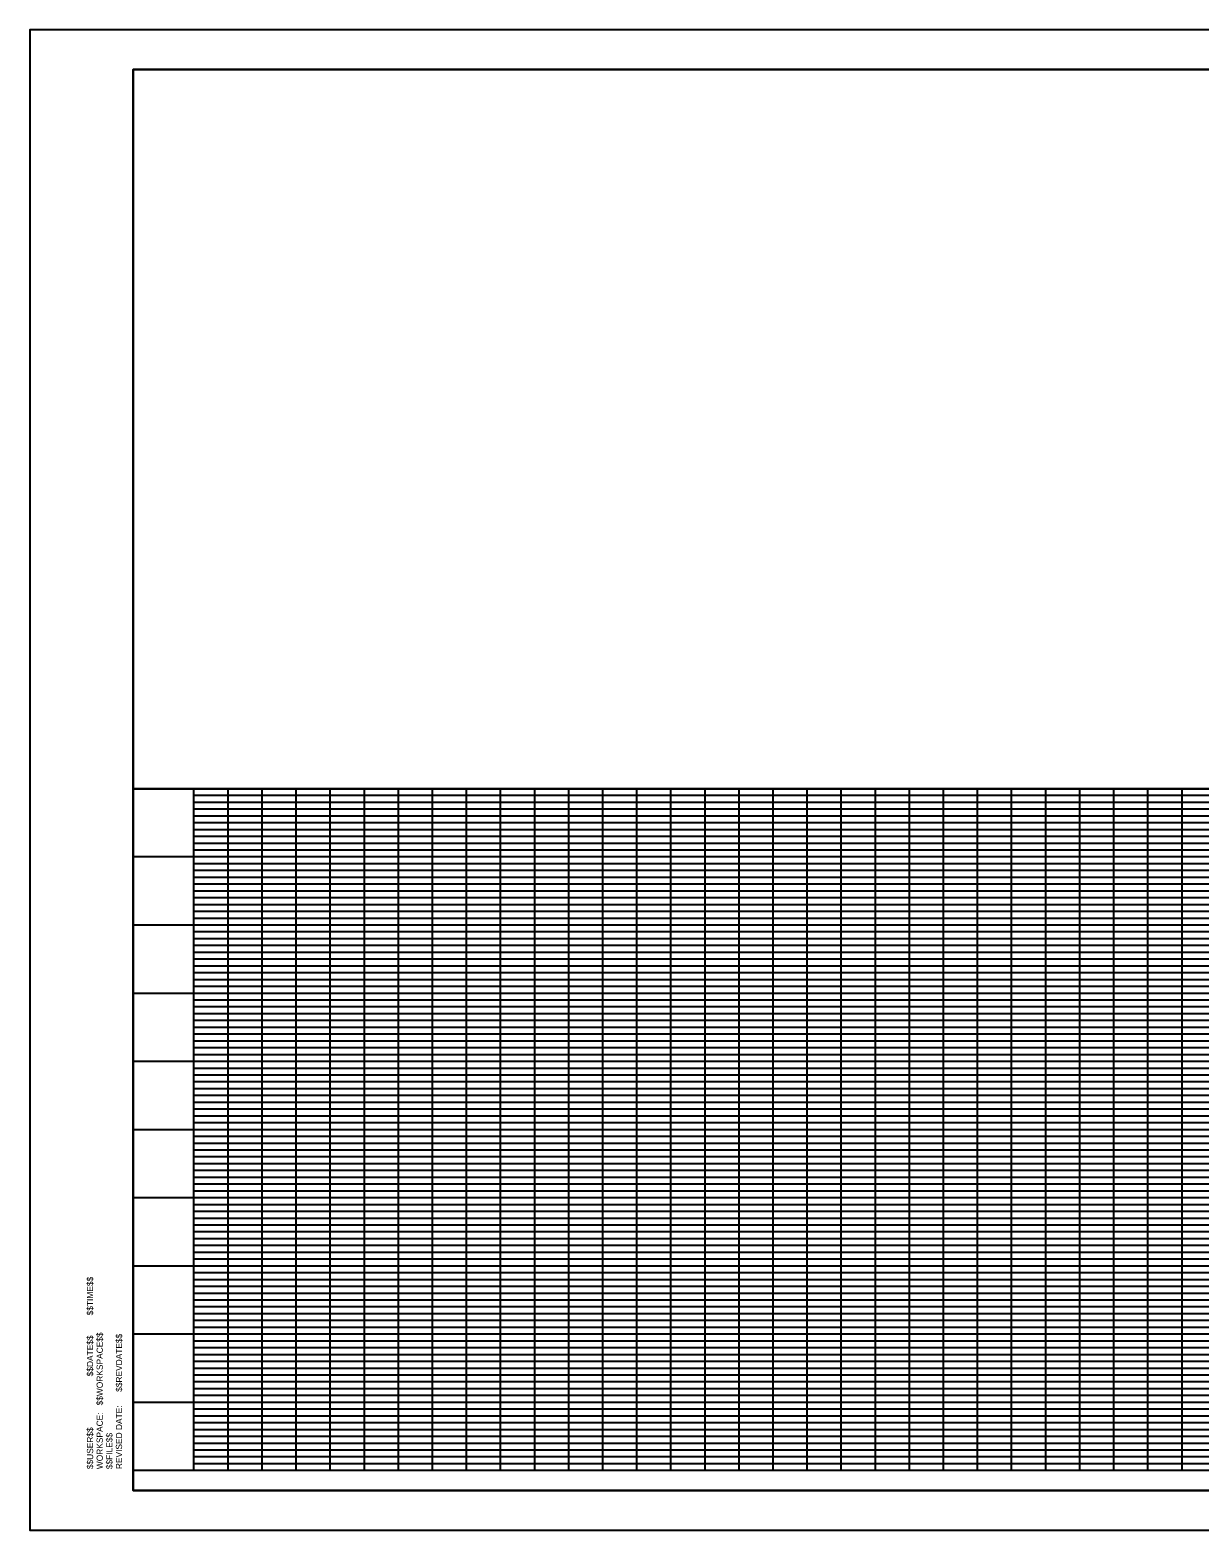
# Model space of a CAD drawing. Extents: x 0 to 1228740, y 0 to 152440.
# Drawn here: x 0 to 17.16, y 0 to 22 of the extents above; entities that cross this region are included whole.
import ezdxf

# ---------------------------------------------------------------- set-up
doc = ezdxf.new("R2010")
doc.units = 0
for name, color, linetype in [('G-TBLK', 7, 'Continuous'), ('R_Border', 7, 'Continuous'), ('R_Grid', 7, 'Continuous'), ('R_No Plot', 7, 'Continuous')]:
    doc.layers.add(name, color=color, linetype=linetype)

msp = doc.modelspace()

# ---------------------------------------------------------------- linework, layer by layer
at = {"layer": 'R_Border'}
for p, q in [((1.516, 21.423), (33.423, 21.423)), ((1.516, 0.577), (1.516, 21.423)), ((33.423, 0.577), (1.516, 0.577))]:
    msp.add_line(p, q, dxfattribs=at)
msp.add_lwpolyline([(34, 22), (0, 22), (0, 0), (34, 0)], close=True, dxfattribs=at)
at = {"layer": 'R_Grid'}
for p, q in [((33.423, 10.871), (1.516, 10.871)), ((2.407, 0.871), (2.407, 10.871)), ((2.907, 0.871), (2.907, 10.871)), ((3.407, 0.871), (3.407, 10.871)), ((3.907, 0.871), (3.907, 10.871)), ((4.407, 0.871), (4.407, 10.871)), ((4.907, 0.871), (4.907, 10.871)), ((5.407, 0.871), (5.407, 10.871)), ((5.907, 0.871), (5.907, 10.871)), ((6.407, 0.871), (6.407, 10.871)), ((6.907, 0.871), (6.907, 10.871)), ((7.407, 0.871), (7.407, 10.871)), ((7.907, 0.871), (7.907, 10.871)), ((8.407, 0.871), (8.407, 10.871)), ((8.907, 0.871), (8.907, 10.871)), ((9.407, 0.871), (9.407, 10.871)), ((9.907, 0.871), (9.907, 10.871)), ((10.407, 0.871), (10.407, 10.871)), ((10.907, 0.871), (10.907, 10.871)), ((11.407, 0.871), (11.407, 10.871)), ((11.907, 0.871), (11.907, 10.871)), ((12.407, 0.871), (12.407, 10.871)), ((12.907, 0.871), (12.907, 10.871)), ((13.407, 0.871), (13.407, 10.871)), ((13.907, 0.871), (13.907, 10.871)), ((14.407, 0.871), (14.407, 10.871)), ((14.907, 0.871), (14.907, 10.871)), ((15.407, 0.871), (15.407, 10.871)), ((15.907, 0.871), (15.907, 10.871)), ((16.407, 0.871), (16.407, 10.871)), ((16.907, 0.871), (16.907, 10.871)), ((32.407, 10.771), (2.407, 10.771)), ((32.407, 10.671), (2.407, 10.671)), ((32.407, 10.571), (2.407, 10.571)), ((32.407, 10.471), (2.407, 10.471)), ((32.407, 10.371), (2.407, 10.371)), ((32.407, 10.271), (2.407, 10.271)), ((32.407, 10.171), (2.407, 10.171)), ((32.407, 10.071), (2.407, 10.071)), ((32.407, 9.971), (2.407, 9.971)), ((33.423, 9.871), (1.516, 9.871)), ((32.407, 9.771), (2.407, 9.771)), ((32.407, 9.671), (2.407, 9.671)), ((32.407, 9.571), (2.407, 9.571)), ((32.407, 9.471), (2.407, 9.471)), ((32.407, 9.371), (2.407, 9.371)), ((32.407, 9.271), (2.407, 9.271)), ((32.407, 9.171), (2.407, 9.171)), ((32.407, 9.071), (2.407, 9.071)), ((33.423, 8.871), (1.516, 8.871)), ((32.407, 8.971), (2.407, 8.971)), ((32.407, 8.771), (2.407, 8.771)), ((32.407, 8.671), (2.407, 8.671)), ((32.407, 8.571), (2.407, 8.571)), ((32.407, 8.471), (2.407, 8.471)), ((32.407, 8.371), (2.407, 8.371)), ((32.407, 8.271), (2.407, 8.271)), ((32.407, 8.171), (2.407, 8.171)), ((32.407, 8.071), (2.407, 8.071)), ((32.407, 7.971), (2.407, 7.971)), ((33.423, 7.871), (1.516, 7.871)), ((32.407, 7.771), (2.407, 7.771)), ((32.407, 7.671), (2.407, 7.671)), ((32.407, 7.571), (2.407, 7.571)), ((32.407, 7.471), (2.407, 7.471)), ((32.407, 7.371), (2.407, 7.371)), ((32.407, 7.271), (2.407, 7.271)), ((32.407, 7.171), (2.407, 7.171)), ((32.407, 7.071), (2.407, 7.071)), ((33.423, 6.871), (1.516, 6.871)), ((32.407, 6.971), (2.407, 6.971)), ((32.407, 6.771), (2.407, 6.771)), ((32.407, 6.671), (2.407, 6.671)), ((32.407, 6.571), (2.407, 6.571)), ((32.407, 6.471), (2.407, 6.471)), ((32.407, 6.371), (2.407, 6.371)), ((32.407, 6.271), (2.407, 6.271)), ((32.407, 6.171), (2.407, 6.171)), ((32.407, 6.071), (2.407, 6.071)), ((32.407, 5.971), (2.407, 5.971)), ((33.423, 5.871), (1.516, 5.871)), ((32.407, 5.771), (2.407, 5.771)), ((32.407, 5.671), (2.407, 5.671)), ((32.407, 5.571), (2.407, 5.571)), ((32.407, 5.471), (2.407, 5.471)), ((32.407, 5.371), (2.407, 5.371)), ((32.407, 5.271), (2.407, 5.271)), ((32.407, 5.171), (2.407, 5.171)), ((32.407, 5.071), (2.407, 5.071)), ((33.423, 4.871), (1.516, 4.871)), ((32.407, 4.971), (2.407, 4.971)), ((32.407, 4.771), (2.407, 4.771)), ((32.407, 4.671), (2.407, 4.671)), ((32.407, 4.571), (2.407, 4.571)), ((32.407, 4.471), (2.407, 4.471)), ((32.407, 4.371), (2.407, 4.371)), ((32.407, 4.271), (2.407, 4.271)), ((32.407, 4.171), (2.407, 4.171)), ((32.407, 4.071), (2.407, 4.071)), ((32.407, 3.971), (2.407, 3.971)), ((33.423, 3.871), (1.516, 3.871)), ((32.407, 3.771), (2.407, 3.771)), ((32.407, 3.671), (2.407, 3.671)), ((32.407, 3.571), (2.407, 3.571)), ((32.407, 3.471), (2.407, 3.471)), ((32.407, 3.371), (2.407, 3.371)), ((32.407, 3.271), (2.407, 3.271)), ((32.407, 3.171), (2.407, 3.171)), ((33.423, 2.871), (1.516, 2.871)), ((32.407, 3.071), (2.407, 3.071)), ((32.407, 2.971), (2.407, 2.971)), ((32.407, 2.771), (2.407, 2.771)), ((32.407, 2.671), (2.407, 2.671)), ((32.407, 2.571), (2.407, 2.571)), ((32.407, 2.471), (2.407, 2.471)), ((32.407, 2.371), (2.407, 2.371)), ((32.407, 2.271), (2.407, 2.271)), ((32.407, 2.171), (2.407, 2.171)), ((32.407, 2.071), (2.407, 2.071)), ((33.423, 1.871), (1.516, 1.871)), ((32.407, 1.971), (2.407, 1.971)), ((32.407, 1.771), (2.407, 1.771)), ((32.407, 1.671), (2.407, 1.671)), ((32.407, 1.571), (2.407, 1.571)), ((32.407, 1.471), (2.407, 1.471)), ((32.407, 1.371), (2.407, 1.371)), ((32.407, 1.271), (2.407, 1.271)), ((32.407, 1.171), (2.407, 1.171)), ((32.407, 1.071), (2.407, 1.071)), ((32.407, 0.971), (2.407, 0.971)), ((33.423, 0.871), (1.516, 0.871))]:
    msp.add_line(p, q, dxfattribs=at)
at = {"layer": 'R_No Plot'}
msp.add_lwpolyline([(33.423, 17.405), (33.423, 10.871), (1.516, 10.871), (1.516, 21.423), (25.197, 21.423), (25.197, 20.435), (28.749, 20.435), (28.749, 20.078), (29.113, 20.078), (29.113, 20.143), (30.667, 20.143)], dxfattribs=at)
for points in [[(1.516, 21.423), (1.516, 0.577), (33.423, 0.577), (33.423, 17.405), (30.667, 17.405), (30.667, 20.143), (29.113, 20.143), (29.113, 20.078), (28.749, 20.078), (28.749, 20.435), (25.197, 20.435), (25.197, 21.423)], [(1.516, 21.423), (25.197, 21.423), (25.197, 20.435), (28.749, 20.435), (28.749, 20.078), (29.113, 20.078), (29.113, 20.143), (30.667, 20.143), (30.667, 17.405), (33.423, 17.405), (33.423, 0.577), (1.516, 0.577)], [(1.516, 10.871), (33.423, 10.871), (33.423, 0.577), (1.516, 0.577)]]:
    msp.add_lwpolyline(points, close=True, dxfattribs=at)

# ---------------------------------------------------------------- texts
at = {"layer": 'G-TBLK'}
for s, p in [('$$TIME$$', (0.927, 3.148)), ('$$WORKSPACE$$', (1.069, 1.827)), ('$$REVDATE$$', (1.352, 2.026)), ('$$DATE$$', (0.927, 2.254)), ('REVISED DATE:', (1.352, 0.893)), ('WORKSPACE:', (1.069, 0.892)), ('$$USER$$', (0.927, 0.892)), ('$$FILE$$', (1.211, 0.892))]:
    msp.add_text(s, height=0.0918, rotation=90, dxfattribs=at).set_placement(p)

doc.saveas('drawing.dxf')
